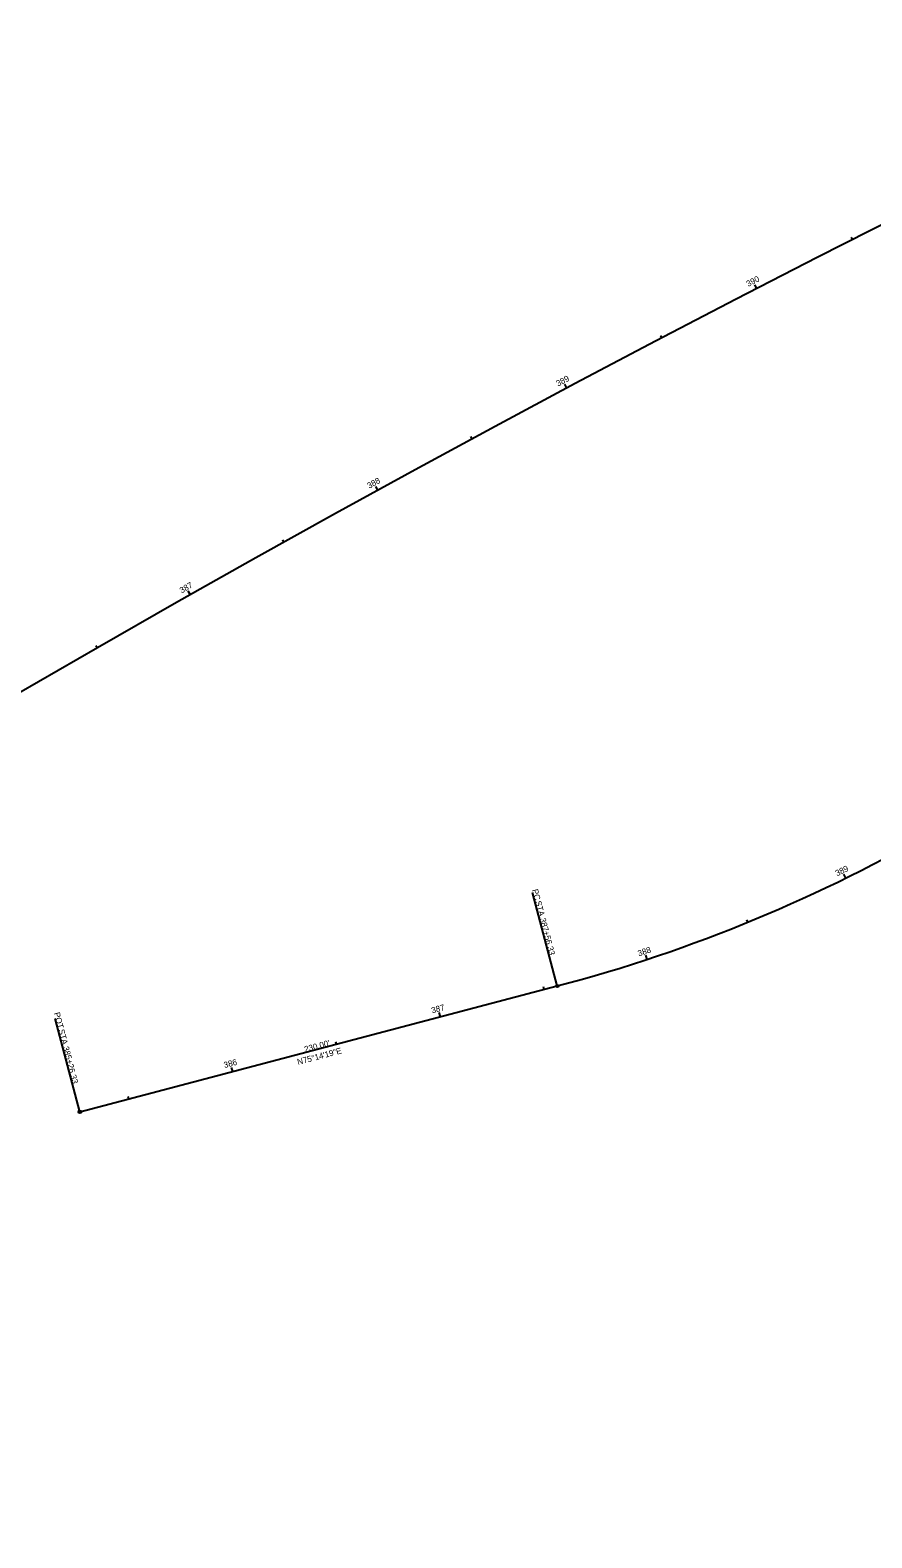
# Model space of a CAD drawing. Extents: x 2138583 to 2143699, y 639707 to 641182.
# Drawn here: x 2139196 to 2139588, y 639745 to 640448 of the extents above; entities that cross this region are included whole.
import ezdxf

# ---------------------------------------------------------------- set-up
doc = ezdxf.new("R2010")
doc.units = 0
for name, color, linetype in [('GE_X_Alignment', 7, 'Continuous'), ('GE_X_Alignment_100_Bearings', 7, 'Continuous'), ('GE_X_Alignment_100_Cardinal_Points', 7, 'Continuous'), ('GE_X_Alignment_100_Distances', 7, 'Continuous'), ('GE_X_Alignment_100_Stations', 7, 'Continuous'), ('RW_X_CL', 7, 'Continuous'), ('RW_X_CL_100_Stations', 7, 'Continuous')]:
    doc.layers.add(name, color=color, linetype=linetype)

msp = doc.modelspace()

# ---------------------------------------------------------------- linework, layer by layer
at = {"layer": 'GE_X_Alignment'}
msp.add_line((2139219.08, 639943.69), (2139441.49, 640002.3), dxfattribs=at)
msp.add_arc((2139259, 640694.86), 716.2, 284.76143, 315.79393, dxfattribs=at)
at = {"layer": 'GE_X_Alignment_100_Cardinal_Points'}
for p, q in [((2139441.49, 640002.3), (2139430.02, 640045.81)), ((2139219.08, 639943.69), (2139207.61, 639987.21))]:
    msp.add_line(p, q, dxfattribs=at)
for centre in [(2139441.49, 640002.3), (2139219.08, 639943.69)]:
    msp.add_circle(centre, 0.6, dxfattribs=at)
at = {"layer": 'GE_X_Alignment_100_Stations'}
for p, q in [((2139575.82, 640052.54), (2139574.94, 640054.34)), ((2139530.25, 640032.01), (2139529.79, 640033.12)), ((2139483.35, 640014.7), (2139482.72, 640016.6)), ((2139435.36, 640000.68), (2139435.06, 640001.84)), ((2139387.02, 639987.94), (2139386.51, 639989.88)), ((2139338.67, 639975.2), (2139338.36, 639976.36)), ((2139290.32, 639962.46), (2139289.81, 639964.4)), ((2139241.97, 639949.72), (2139241.66, 639950.88))]:
    msp.add_line(p, q, dxfattribs=at)
at = {"layer": 'RW_X_CL'}
msp.add_arc((2143034.99, 633536.97), 7639.44, 85.029584, 125.643473, dxfattribs=at)
at = {"layer": 'RW_X_CL_100_Stations'}
for p, q in [((2139578.99, 640349.98), (2139578.45, 640351.05)), ((2139534.48, 640327.22), (2139533.56, 640328.99)), ((2139490.11, 640304.16), (2139489.55, 640305.22)), ((2139445.9, 640280.81), (2139444.96, 640282.58)), ((2139401.83, 640257.18), (2139401.26, 640258.23)), ((2139357.93, 640233.26), (2139356.97, 640235.01)), ((2139314.18, 640209.05), (2139313.6, 640210.09)), ((2139270.59, 640184.55), (2139269.61, 640186.29)), ((2139227.16, 640159.77), (2139226.57, 640160.81))]:
    msp.add_line(p, q, dxfattribs=at)

# ---------------------------------------------------------------- texts
at = {"layer": 'GE_X_Alignment_100_Bearings'}
msp.add_text('N75°14\'19"E', height=2.8, rotation=14.76143, dxfattribs=at).set_placement((2139320.75, 639965.52))
at = {"layer": 'GE_X_Alignment_100_Cardinal_Points'}
for s, p in [('PC', (2139429.73, 640047.05)), (' STA. ', (2139430.91, 640042.6)), ('387+56.33', (2139433.28, 640033.58)), ('POT', (2139207, 639989.67)), (' STA. ', (2139208.82, 639982.77)), ('385+26.33', (2139211.19, 639973.76))]:
    msp.add_text(s, height=2.8, rotation=284.76143, dxfattribs=at).set_placement(p)
at = {"layer": 'GE_X_Alignment_100_Distances'}
msp.add_text("230.00'", height=2.8, rotation=14.76143, dxfattribs=at).set_placement((2139324.05, 639971.39))
at = {"layer": 'GE_X_Alignment_100_Stations'}
for s, rotation, p in [('389', 26.25499, (2139571.83, 640053.36)), ('388', 18.25502, (2139479.48, 640016.06)), ('387', 14.76143, (2139383.24, 639989.53)), ('386', 14.76143, (2139286.53, 639964.05))]:
    msp.add_text(s, height=2.8, rotation=rotation, dxfattribs=at).set_placement(p)
at = {"layer": 'RW_X_CL_100_Stations'}
for s, rotation, p in [('390', 27.27205, (2139530.43, 640327.94)), ('389', 28.02205, (2139441.87, 640281.5)), ('388', 28.77205, (2139353.88, 640233.88)), ('387', 29.52205, (2139266.54, 640185.13))]:
    msp.add_text(s, height=2.8, rotation=rotation, dxfattribs=at).set_placement(p)

doc.saveas('drawing.dxf')
